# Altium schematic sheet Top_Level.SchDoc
size A4; Organization: Altium Limited; Address1: L3, 12a Rodborough Rd; Address2: Frenchs Forest; Address3: NSW; Address4: Australia 2086
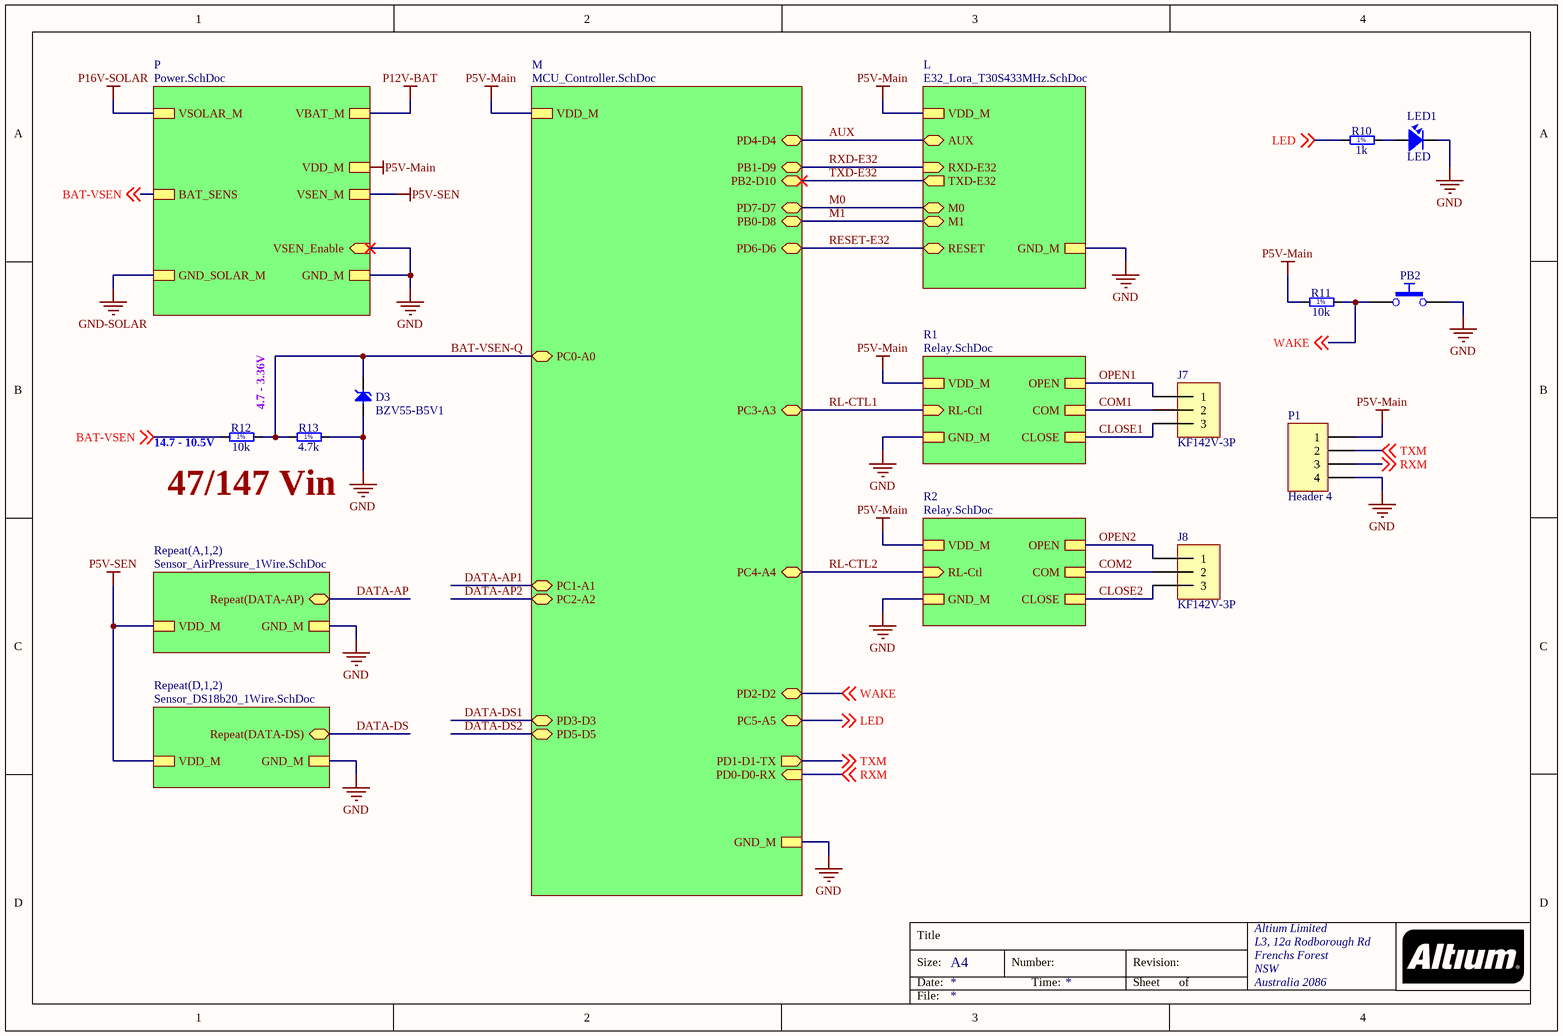
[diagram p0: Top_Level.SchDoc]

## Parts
D3  BZV55-B5V1  [DIOMELF3515N]
J7  KF142V-3P  [CON KF142V-3P-5.08]
J8  KF142V-3P  [CON KF142V-3P-5.08]
LED1  LED  [L-0805]
P1  Header 4  [HDR1X4]
PB2  Push Button  [PB_TYCO_FSMSM]  (value not drawn)
R10  1k  [RESC1608X55N]
R11  10k  [RESC1608X55N]
R12  10k  [RESC1608X55N]
R13  4.7k  [RESC1608X55N]

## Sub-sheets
L = E32_Lora_T30S433MHz.SchDoc: M0 (bidir), M1 (bidir), RESET (bidir), AUX (bidir), GND_M, VDD_M, RXD-E32 (in), TXD-E32 (out)
M = MCU_Controller.SchDoc: PB1-D9 (bidir), PB2-D10 (bidir), GND_M, PC3-A3 (bidir), PB0-D8 (bidir), PD6-D6 (bidir), PD2-D2 (bidir), PC4-A4 (bidir), PD4-D4 (bidir), PC5-A5 (bidir), PC2-A2 (bidir), PD0-D0-RX (in), PD3-D3 (bidir), PC1-A1 (bidir), PD7-D7 (bidir), VDD_M, PD5-D5 (bidir), PC0-A0 (bidir), PD1-D1-TX (out)
P = Power.SchDoc: VSOLAR_M, VSEN_Enable (in), BAT_SENS, VSEN_M, GND_SOLAR_M, VBAT_M, GND_M, VDD_M
R1 = Relay.SchDoc: OPEN, GND_M, CLOSE, RL-Ctl (in), VDD_M, COM
R2 = Relay.SchDoc: OPEN, GND_M, CLOSE, RL-Ctl (in), VDD_M, COM
Repeat(A,1,2) = Sensor_AirPressure_1Wire.SchDoc: VDD_M, GND_M, Repeat(DATA-AP) (bidir)
Repeat(D,1,2) = Sensor_DS18b20_1Wire.SchDoc: GND_M, Repeat(DATA-DS) (bidir), VDD_M

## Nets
GND: D3.2(A) LED1.2 P1.4 PB2.2 R13.2 ; sheet M/GND_M, sheet L/GND_M, sheet P/VSEN_Enable, sheet P/GND_M, sheet Repeat(A,1,2)/GND_M, sheet Repeat(D,1,2)/GND_M, sheet R1/GND_M, sheet R2/GND_M
P5V-Main: P1.1 R11.1 ; sheet M/VDD_M, sheet L/VDD_M, sheet P/VDD_M, sheet R1/VDD_M, sheet R2/VDD_M
P5V-SEN: sheet P/VSEN_M, sheet Repeat(A,1,2)/VDD_M, sheet Repeat(D,1,2)/VDD_M
AUX: sheet M/PD4-D4, sheet L/AUX
BAT-VSEN: R12.1 ; off-sheet BAT-VSEN, sheet P/BAT_SENS
BAT-VSEN-Q: D3.1(C) R12.2 R13.1 ; sheet M/PC0-A0
CLOSE1: J7.3 ; sheet R1/CLOSE
CLOSE2: J8.3 ; sheet R2/CLOSE
COM1: J7.2 ; sheet R1/COM
COM2: J8.2 ; sheet R2/COM
LED: R10.1 ; off-sheet LED, sheet M/PC5-A5
M0: sheet M/PD7-D7, sheet L/M0
M1: sheet M/PB0-D8, sheet L/M1
OPEN1: J7.1 ; sheet R1/OPEN
OPEN2: J8.1 ; sheet R2/OPEN
RESET-E32: sheet M/PD6-D6, sheet L/RESET
RL-CTL1: sheet M/PC3-A3, sheet R1/RL-Ctl
RL-CTL2: sheet M/PC4-A4, sheet R2/RL-Ctl
RXD-E32: sheet M/PB1-D9, sheet L/RXD-E32
RXM: P1.3 ; off-sheet RXM, sheet M/PD0-D0-RX
TXD-E32: sheet M/PB2-D10, sheet L/TXD-E32
TXM: P1.2 ; off-sheet TXM, sheet M/PD1-D1-TX
WAKE: PB2.1 R11.2 ; off-sheet WAKE, sheet M/PD2-D2
NetLED1_1: LED1.1 R10.2

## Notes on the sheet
- (near R12) 14.7 - 10.5V
- 4.7 - 3.36V
- 47/147 Vin

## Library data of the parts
D3 = BZV55-B5V1: Zener Diode; Part Description: Voltage Regulator Diode; Manufacturer: NXP SEMICONDUCTORS; Voltage: 5V1; Power: 500mW; Table: Diodes
J7 J8 = CON KF142V-3P-5.08
LED1 = LED: LED Single colour Green and Red; Value: LED 3 ly Single Colour
P1 = Header 4: Header, 4-Pin
PB2 = PB SPST 1NO-2NO: Push-Button Switch SPDT; Part Description: 12VDC 50mA SPST Tactile  Push-Button Switch; Manufacturer: TYCO ELECTRONICS; Manufacturer Part Number: FSMSM or 1437566-3; Table: Switches
R10 = R0603_200R_1%_0.1W_100PPM: Resistor - 1%; Part Description: General Purpose Thick Film Chip Resistor; Manufacturer: GENERIC; Manufacturer1 Part Number: NRC06F2000TRF; Value: 200; Power: 0.1W; TC: ±100ppm/°C; Table: Resistors SMD
R11 = R0603_10K_1%_0.1W_100PPM: Resistor - 1%; Part Description: General Purpose Thick Film Chip Resistor; Manufacturer: GENERIC; Manufacturer1 Part Number: NRC06F1002TRF; Power: 0.1W; TC: ±100ppm/°C; Table: Resistors SMD
R12 = R0603_2M_1%_0.1W_100PPM: Resistor - 1%; Part Description: General Purpose Thick Film Chip Resistor; Manufacturer: GENERIC; Manufacturer1 Part Number: NRC06F2004TRF; Value: 2M; Power: 0.1W; TC: ±100ppm/°C; Table: Resistors SMD
R13 = R0603_1M_1%_0.1W_100PPM: Resistor - 1%; Part Description: General Purpose Thick Film Chip Resistor; Manufacturer: GENERIC; Manufacturer1 Part Number: NRC06F1004TRF; Value: 1M; Power: 0.1W; TC: ±100ppm/°C; Table: Resistors SMD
